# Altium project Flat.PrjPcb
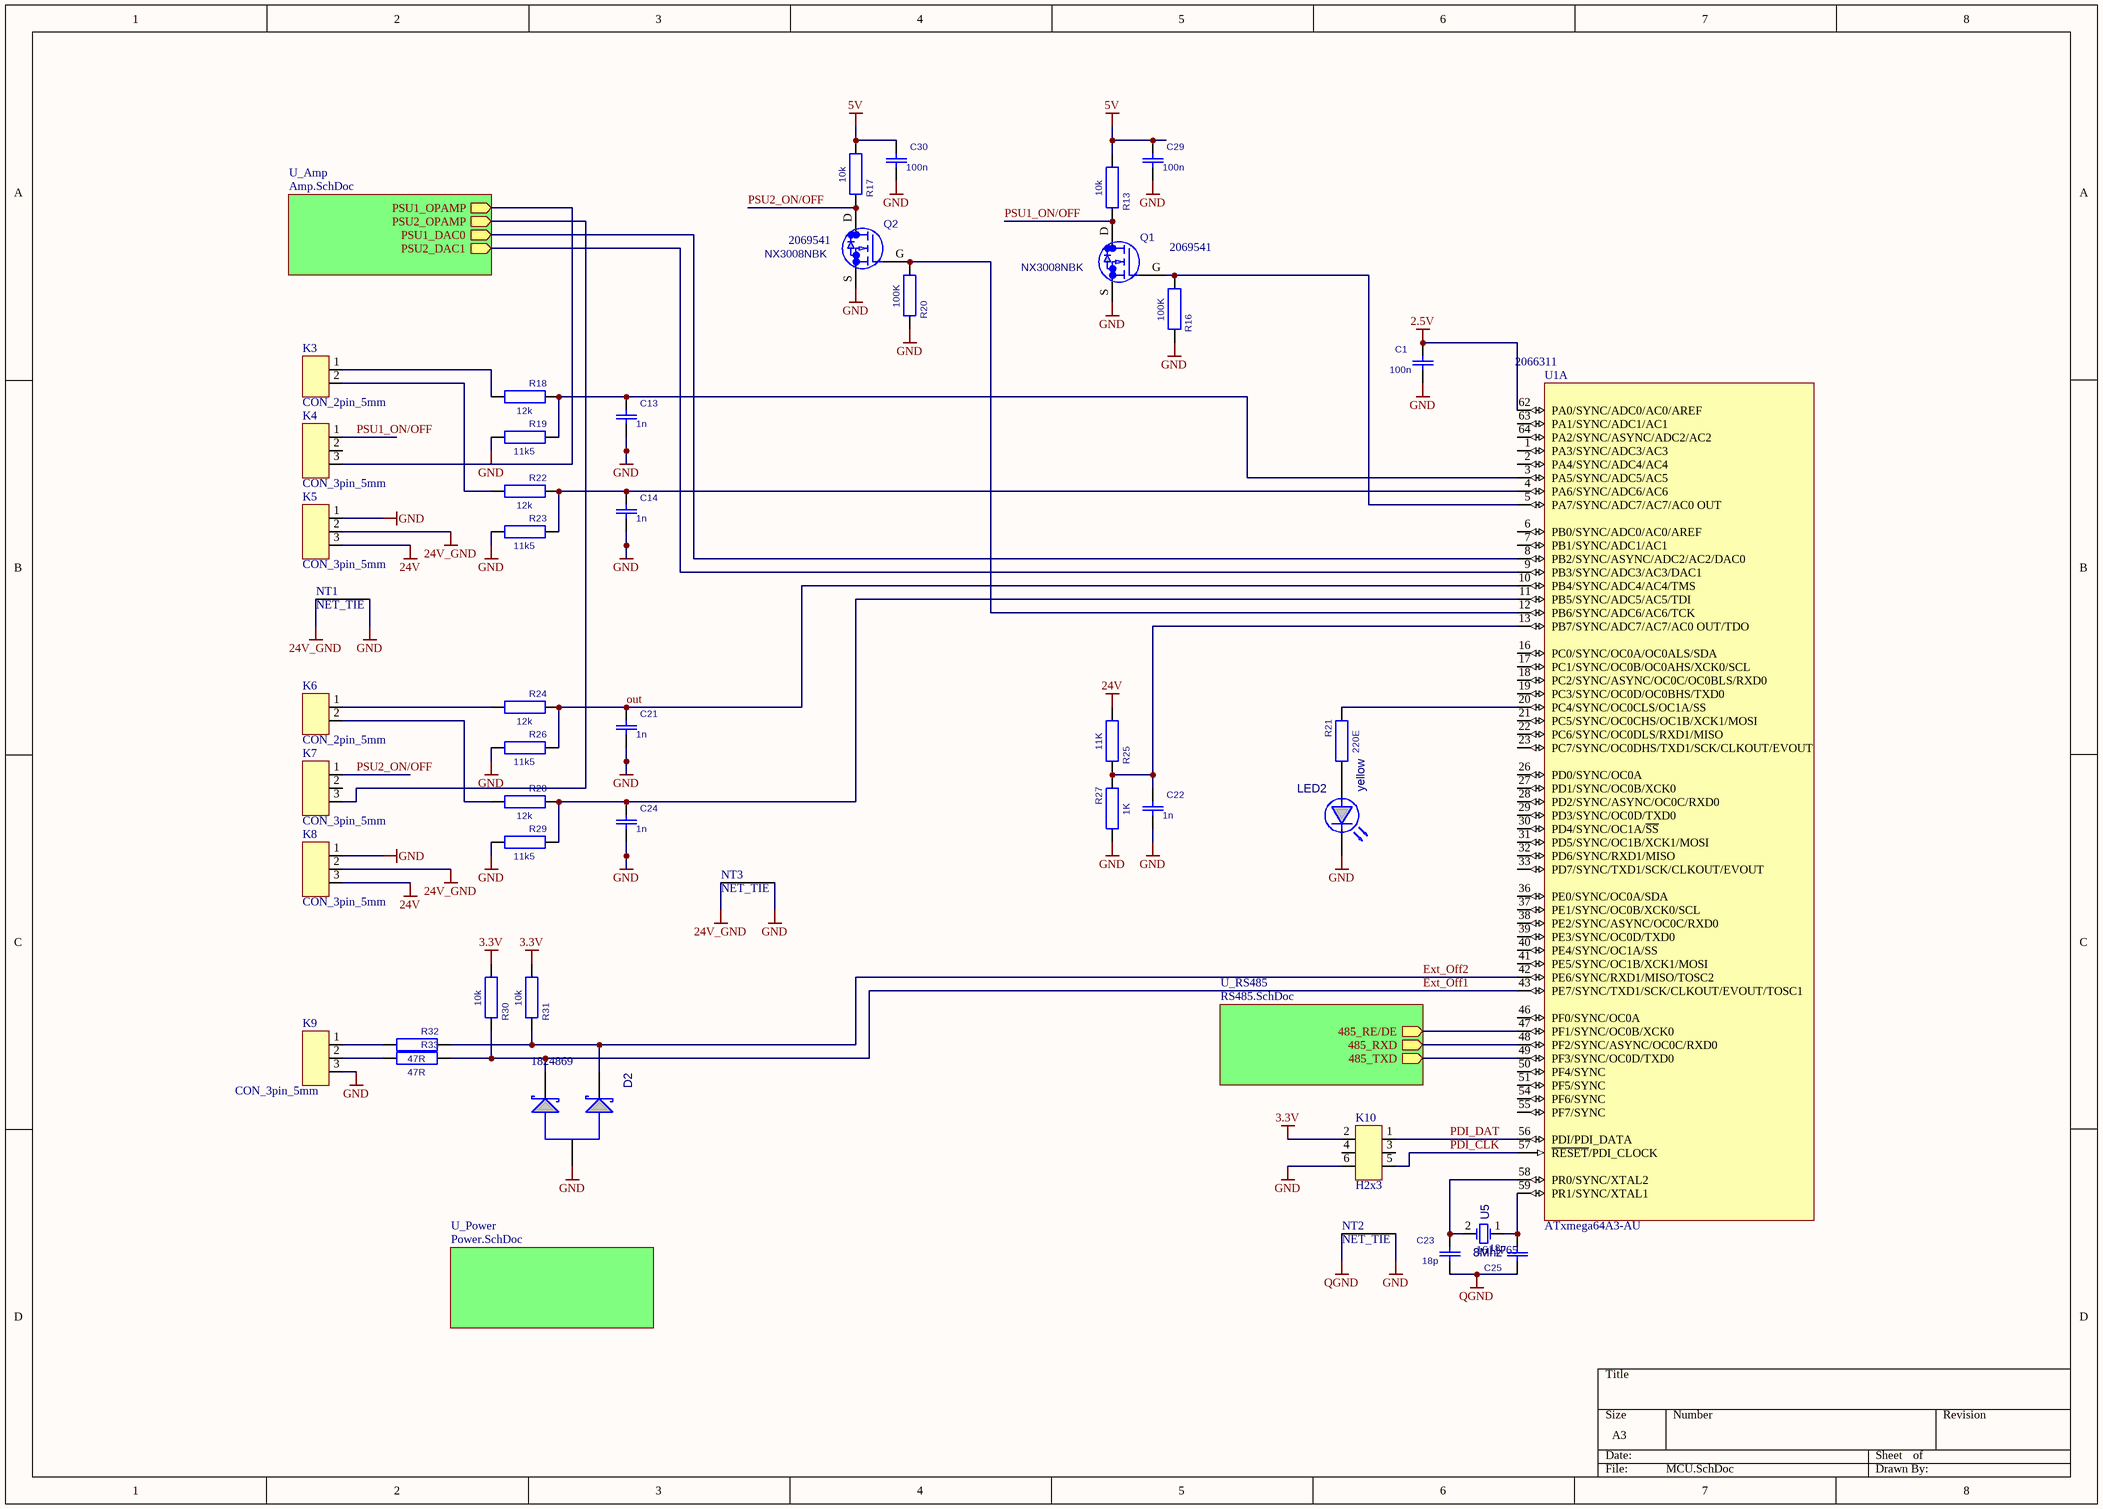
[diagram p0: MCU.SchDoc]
4 sheets, 95 parts. Net scope: hierarchical (ports join the sheet entries above them; power ports are global).
Board file: Flat.PcbDoc
Sheets:
  MCU.SchDoc
    U_Amp = Amp.SchDoc
    U_Power = Power.SchDoc
    U_RS485 = RS485.SchDoc

## Sheet MCU.SchDoc
size A3; SheetNumber: 1; SheetTotal: 4

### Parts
C1  100n  [C0805]
C13  1n  [C0805]
C14  1n  [C0805]
C21  1n  [C0805]
C22  1n  [C0805]
C23  18p  [C0805]
C24  1n  [C0805]
C25  18p  [C0805]
C29  100n  [C0805]
C30  100n  [C0805]
D2  Supplier Part Number 1: 1824869  [SOT-663]  (hidden comment: CDSOT23-SM712)
K3  CON_2pin_5mm  [CON_2pin_5mm]
K4  CON_3pin_5mm  [COM_3pin_5mm]
K5  CON_3pin_5mm  [COM_3pin_5mm]
K6  CON_2pin_5mm  [CON_2pin_5mm]
K7  CON_3pin_5mm  [COM_3pin_5mm]
K8  CON_3pin_5mm  [COM_3pin_5mm]
K9  CON_3pin_5mm  [COM_3pin_5mm]
K10  H2x3  [H2x3]
LED2  value yellow  [LED0805]  (hidden comment: LED0805)
NT1  NET_TIE  [NET_TIE_LINE]  (net tie, no BOM)
NT2  NET_TIE  [NET_TIE_LINE]  (net tie, no BOM)
NT3  NET_TIE  [NET_TIE_LINE]  (net tie, no BOM)
Q1  NX3008NBK  Supplier Part Number 1: 2069541  [SOT23(IRLML2502)]
Q2  NX3008NBK  Supplier Part Number 1: 2069541  [SOT23(IRLML2502)]
R13  10k  [R0805]
R16  100K  [R0805]
R17  10k  [R0805]
R18  12k  [R0805]
R19  11k5  [R0805]
R20  100K  [R0805]
R21  220E  [R0805]
R22  12k  [R0805]
R23  11k5  [R0805]
R24  12k  [R0805]
R25  11K  [R0805]
R26  11k5  [R0805]
R27  1K  [R0805]
R28  12k  [R0805]
R29  11k5  [R0805]
R30  10k  [R0805]
R31  10k  [R0805]
R32  47R  [R0805]
R33  47R  [R0805]
U1  ATxmega64A3-AU  Supplier Part Number 1: 2066311  [64A_M]  (part A of 2)
U5  8Mhz  Supplier Part Number 1: 1611765  [HC49/4H_SMX]

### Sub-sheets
U_Amp = Amp.SchDoc: PSU1_OPAMP (out), PSU2_OPAMP (out), PSU1_DAC0 (out), PSU2_DAC1 (out)
U_Power = Power.SchDoc: no entries
U_RS485 = RS485.SchDoc: 485_RE/DE (out), 485_TXD (out), 485_RXD (out)

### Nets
2.5V: C1.1 U1.62(PA0/SYNC/ADC0/AC0/AREF)
3.3V: K10.2 R30.2 R31.2
5V: C29.1 C30.1 R13.2 R17.2
24V: K5.3 K8.3 R25.2
24V_GND: K5.2 K8.2 NT1.1 NT3.1
GND: C1.2 C13.2 C14.2 C21.2 C22.2 C24.2 C29.2 C30.2 D2.2(A2) K5.1 K8.1 K9.3 K10.6 LED2.K NT1.2 NT2.2 NT3.2 Q1.S Q2.S R16.1 R19.2 R20.1 R23.2 R26.2 R27.2 R29.2
QGND: C23.2 C25.1 NT2.1
485_RE/DE: U1.47(PF1/SYNC/OC0B/XCK0) ; sheet U_RS485/485_RE/DE
485_RXD: U1.48(PF2/SYNC/ASYNC/OC0C/RXD0) ; sheet U_RS485/485_RXD
485_TXD: U1.49(PF3/SYNC/OC0D/TXD0) ; sheet U_RS485/485_TXD
Ext_Off1: D2.3(K) R30.1 R33.1 U1.43(PE7/SYNC/TXD1/SCK/CLKOUT/EVOUT/TOSC1)  [project net Ext_Off1_1]
Ext_Off2: D2.1(A1) R31.1 R32.1 U1.42(PE6/SYNC/RXD1/MISO/TOSC2)  [project net Ext_Off2_1]
out: C21.1 R24.1 R26.1 U1.10(PB4/SYNC/ADC4/AC4/TMS)  [project net out_1]
PDI_CLK: K10.5 U1.57(~{RESET}/PDI_CLOCK)  [project net PDI_CLK_1]
PDI_DAT: K10.1 U1.56(PDI/PDI_DATA)  [project net PDI_DAT_1]
PSU1_DAC0: U1.8(PB2/SYNC/ASYNC/ADC2/AC2/DAC0) ; sheet U_Amp/PSU1_DAC0
PSU1_ON/OFF: K4.1 Q1.D R13.1  [project net PSU1_ON/OFF_1]
PSU1_OPAMP: K4.3 ; sheet U_Amp/PSU1_OPAMP
PSU2_DAC1: U1.9(PB3/SYNC/ADC3/AC3/DAC1) ; sheet U_Amp/PSU2_DAC1
PSU2_ON/OFF: K7.1 Q2.D R17.1  [project net PSU2_ON/OFF_1]
PSU2_OPAMP: K7.3 ; sheet U_Amp/PSU2_OPAMP
NetC13_1: C13.1 R18.1 R19.1 U1.3(PA5/SYNC/ADC5/AC5)
NetC14_1: C14.1 R22.1 R23.1 U1.4(PA6/SYNC/ADC6/AC6)
NetC22_1: C22.1 R25.1 R27.1 U1.13(PB7/SYNC/ADC7/AC7/AC0_OUT/TDO)
NetC23_1: C23.1 U1.58(PR0/SYNC/XTAL2) U5.2(OSC2)
NetC24_1: C24.1 R28.1 R29.1 U1.11(PB5/SYNC/ADC5/AC5/TDI)
NetC25_2: C25.2 U1.59(PR1/SYNC/XTAL1) U5.1(OSC1)
NetK3_1: K3.1 R18.2
NetK3_2: K3.2 R22.2
NetK6_1: K6.1 R24.2
NetK6_2: K6.2 R28.2
NetK9_1: K9.1 R32.2
NetK9_2: K9.2 R33.2
NetLED2_A: LED2.A R21.2
NetQ1_G: Q1.G R16.2 U1.5(PA7/SYNC/ADC7/AC7/AC0_OUT)
NetQ2_G: Q2.G R20.2 U1.12(PB6/SYNC/ADC6/AC6/TCK)
NetR21_1: R21.1 U1.20(PC4/SYNC/OC0CLS/OC1A/SS)

Not connected (* = marked no-connect by the designer): K4 2; K7 2; K10 3 4; U1 1(PA3/SYNC/ADC3/AC3) 2(PA4/SYNC/ADC4/AC4) 6(PB0/SYNC/ADC0/AC0/AREF) 7(PB1/SYNC/ADC1/AC1) 16(PC0/SYNC/OC0A/OC0ALS/SDA) 17(PC1/SYNC/OC0B/OC0AHS/XCK0/SCL) 18(PC2/SYNC/ASYNC/OC0C/OC0BLS/RXD0) 19(PC3/SYNC/OC0D/OC0BHS/TXD0) 21(PC5/SYNC/OC0CHS/OC1B/XCK1/MOSI) 22(PC6/SYNC/OC0DLS/RXD1/MISO) 23(PC7/SYNC/OC0DHS/TXD1/SCK/CLKOUT/EVOUT) 26(PD0/SYNC/OC0A) 27(PD1/SYNC/OC0B/XCK0) 28(PD2/SYNC/ASYNC/OC0C/RXD0) 29(PD3/SYNC/OC0D/TXD0) 30(PD4/SYNC/OC1A/~{SS}) 31(PD5/SYNC/OC1B/XCK1/MOSI) 32(PD6/SYNC/RXD1/MISO) 33(PD7/SYNC/TXD1/SCK/CLKOUT/EVOUT) 36(PE0/SYNC/OC0A/SDA) 37(PE1/SYNC/OC0B/XCK0/SCL) 38(PE2/SYNC/ASYNC/OC0C/RXD0) 39(PE3/SYNC/OC0D/TXD0) 40(PE4/SYNC/OC1A/SS) 41(PE5/SYNC/OC1B/XCK1/MOSI) 46(PF0/SYNC/OC0A) 50(PF4/SYNC) 51(PF5/SYNC) 54(PF6/SYNC) 55(PF7/SYNC) 63(PA1/SYNC/ADC1/AC1) 64(PA2/SYNC/ASYNC/ADC2/AC2)

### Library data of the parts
C1 C13 C14 C21-C25 C29 C30 = SMD CAPACITOR: SMD Chip Capacitor; Tolerance: {Tolerance}
D2 = BAT54A: pin to pad: 2>3 3>2; ComponentLink2DescA4: Datasheet; Note: Pin 2 is not connected and is not drawn; ComponentLink1DescBC: Manufacturer Link
K3 K6 = CON_2pin_5mm: Konektor za  Bernic ohišja Serija 605, 5 mm raster
K4 K5 K7-K9 = CON_3pin_5mm: Konektor za Bernic ohišja, 5 mm
K10 = H2x3: Header 2x3 (male)
LED2 = LED0805: Chip LED diode
Q1 Q2 = IRLML2502: Value: {Value}
R13 R16-R33 = SMD RESISTOR: Surface mount resistor; Power: {Power}
U1 = ATxmega64A3-AU: 8/16-bit AVR XMEGA A3 Microcontroller, 1.6-3.6V, 32MHz, 64KB + 4KB Flash, 2KB EEPROM, 4KB SRAM, 64-pin TQFP, Industrial Grade (-40°C to 85°C), Pb-Free
U5 = Q HC49 SMD: Q SMD; ComponentLink2DescA4: Datasheet; Note: PCB layout complies with manufacturer's recommendation.; ComponentLink1DescBC: Manufacturer Link

## Sheet Amp.SchDoc
size A4; SheetNumber: 3; SheetTotal: 4
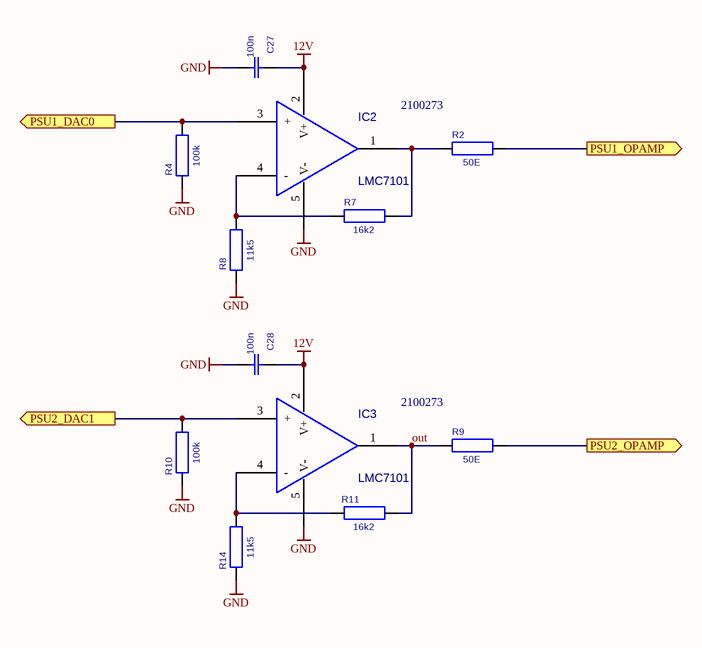
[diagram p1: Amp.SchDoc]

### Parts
C27  100n  [C0805]
C28  100n  [C0805]
IC2  LMC7101  Supplier Part Number 1: 2100273  [SO-G5/P.95]
IC3  LMC7101  Supplier Part Number 1: 2100273  [SO-G5/P.95]
R2  50E  [R0805]
R4  100k  [R0805]
R7  16k2  [R0805]
R8  11k5  [R0805]
R9  50E  [R0805]
R10  100k  [R0805]
R11  16k2  [R0805]
R14  11k5  [R0805]

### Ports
PSU1_DAC0 (out), PSU1_OPAMP (out), PSU2_DAC1 (out), PSU2_OPAMP (out)

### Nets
12V: C27.1 C28.1 IC2.2(V+) IC3.2(V+)
GND: C27.2 C28.2 IC2.5(V-) IC3.5(V-) R4.1 R8.1 R10.1 R14.1
out: IC3.1 R9.1 R11.2  [project net out_3]
PSU1_DAC0: IC2.3(+) R4.2 ; port PSU1_DAC0
PSU1_OPAMP: R2.2 ; port PSU1_OPAMP
PSU2_DAC1: IC3.3(+) R10.2 ; port PSU2_DAC1
PSU2_OPAMP: R9.2 ; port PSU2_OPAMP
NetIC2_1: IC2.1 R2.1 R7.2
NetIC2_4: IC2.4(-) R7.1 R8.2
NetIC3_4: IC3.4(-) R11.1 R14.2

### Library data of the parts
C27 C28 = SMD CAPACITOR: as C1 on sheet MCU
R2 R4 R7-R11 R14 = SMD RESISTOR: Surface mount resistor; Power: {Power}

## Sheet Power.SchDoc
size A4; SheetNumber: 4; SheetTotal: 4
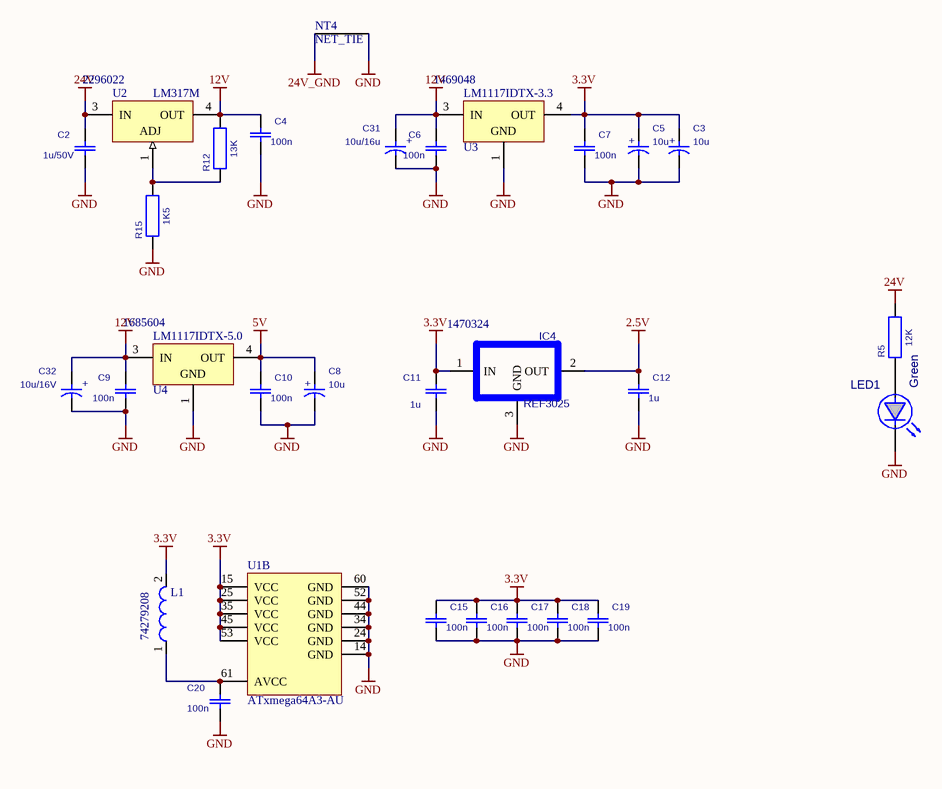
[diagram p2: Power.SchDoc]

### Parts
C2  1u/50V  [C0805]
C3  10u  [CT_A]
C4  100n  [C0805]
C5  10u  [CT_A]
C6  100n  [C0805]
C7  100n  [C0805]
C8  10u  [CT_A]
C9  100n  [C0805]
C10  100n  [C0805]
C11  1u  [C0805]
C12  1u  [C0805]
C15  100n  [C0805]
C16  100n  [C0805]
C17  100n  [C0805]
C18  100n  [C0805]
C19  100n  [C0805]
C20  100n  [C0805]
C31  10u/16u  [CT_A]
C32  10u/16V  [CT_A]
IC4  REF3025  Supplier Part Number 1: 1470324  [SOT23]
L1  74279208  [SMD-0805]
LED1  value Green  [LED0805]  (hidden comment: LED0805)
NT4  NET_TIE  [NET_TIE_LINE]  (net tie, no BOM)
R5  12K  [R0805]
R12  13K  [R0805]
R15  1K5  [R0805]
U1  ATxmega64A3-AU  [64A_N]  (part B of 2)
U2  LM317M  Supplier Part Number 1: 2296022  [TD03B_M]
U3  LM1117IDTX-3.3  Supplier Part Number 1: 1469048  [TD03B_M]
U4  LM1117IDTX-5.0  Supplier Part Number 1: 1685604  [TD03B_M]

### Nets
2.5V: C12.1 IC4.2(OUT)
3.3V: C3.1 C5.1 C7.1 C11.1 C15.1 C16.1 C17.1 C18.1 C19.1 IC4.1(IN) L1.2 U1.15(VCC) U1.25(VCC) U1.35(VCC) U1.45(VCC) U1.53(VCC) U3.4(OUT)
5V: C8.1 C10.1 U4.4(OUT)
12V: C4.1 C6.1 C9.1 C31.1 C32.1 R12.2 U2.4(OUT) U3.3(IN) U4.3(IN)
24V: C2.1 R5.2 U2.3(IN)
24V_GND: NT4.1
GND: C2.2 C3.2 C4.2 C5.2 C6.2 C7.2 C8.2 C9.2 C10.2 C11.2 C12.2 C15.2 C16.2 C17.2 C18.2 C19.2 C20.2 C31.2 C32.2 IC4.3(GND) LED1.K NT4.2 R15.1 U1.14(GND) U1.24(GND) U1.34(GND) U1.44(GND) U1.52(GND) U1.60(GND) U3.1(GND) U4.1(GND)
NetC20_1: C20.1 L1.1 U1.61(AVCC)
NetLED1_A: LED1.A R5.1
NetR12_1: R12.1 R15.2 U2.1(ADJ)

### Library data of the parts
C2 C4 C6 C7 C9-C12 C15-C20 = SMD CAPACITOR: as C1 on sheet MCU
C3 C5 C8 C31 C32 = CT_A: {Description}; RefProducer: {RefProducer}; Geometry: {Geometry}; Tolerance: {Tolerance}; MinESR: {MinESR}; MaxESR: {MaxESR}; SolventProof: {SolventProof}; LifeTime: {LifeTime}; TempRange: {TempRange}; Reference: {Reference}; RefProducerCode: {RefProducerCode}; Z(-25deg)/Z(+20deg): {Z(-25deg)/Z(+20deg)}; MaxLeakageCurrent: {MaxLeakageCurrent}; MinRippleCurrent: {MinRippleCurrent}
IC4 = REF3040
L1 = 74279208: SMD EMI Suppression Ferrite Bead WE-CBF, Z = 40 Ohm; Impedance: 40 Ohm
LED1 = LED0805: Chip LED diode
R5 R12 R15 = SMD RESISTOR: Surface mount resistor; Power: {Power}
U1 = ATxmega64A3-AU: as U1 on sheet MCU
U2 = LM317MDT: 3-Terminal Adjustable Regulator, 3-pin TO-252; Manufacturer: National Semiconductor; PackageTopMarking: NSUZXYTT*LM317*MDT; PowerWise: N; CompType: LDO IC; High-Reliability: Y
U3 = LM1117IDTX-3.3: 800mA Low-Dropout Linear Regulator, 3-pin TO-252; Manufacturer: National Semiconductor; PackageTopMarking: NSUZXYTT*LM1117*IDT-3.3; PowerWise: N; CompType: LDO IC; High-Reliability: Y
U4 = LM1117IDTX-5.0: 800mA Low-Dropout Linear Regulator, 3-pin TO-252; Manufacturer: National Semiconductor; PackageTopMarking: NSUZXYTT*LM1117*IDT-5.0; PowerWise: N; CompType: LDO IC; High-Reliability: Y

## Sheet RS485.SchDoc
size A4; SheetNumber: 2; SheetTotal: 4
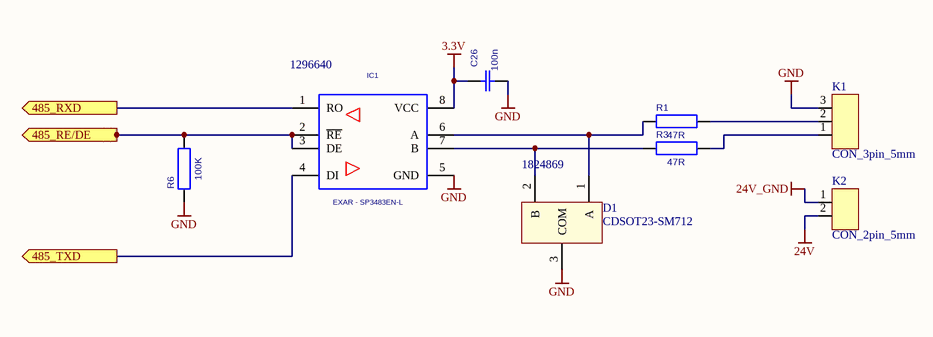
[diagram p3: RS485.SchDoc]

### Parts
C26  100n  [C0805]
D1  CDSOT23-SM712  Supplier Part Number 2: 1824869  [SOT23(BAT54)]
IC1  EXAR - SP3483EN-L  Supplier Part Number 1: 1296640  [SO8R]
K1  CON_3pin_5mm  [COM_3pin_5mm]
K2  CON_2pin_5mm  [CON_2pin_5mm]
R1  47R  [R0805]
R3  47R  [R0805]
R6  100K  [R0805]

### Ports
485_RE/DE (out), 485_RXD (out), 485_TXD (out)

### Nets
3.3V: C26.1 IC1.8(VCC)
24V: K2.2
24V_GND: K2.1
GND: C26.2 D1.3(COM) IC1.5(GND) K1.3 R6.1
485_RE/DE: IC1.2(~{RE}) IC1.3(DE) R6.2 ; off-sheet 485_RE/DE, port 485_RE/DE
485_RXD: IC1.1(RO) ; port 485_RXD
485_TXD: IC1.4(DI) ; port 485_TXD
NetD1_1: D1.1(A) IC1.6(A) R1.1
NetD1_2: D1.2(B) IC1.7(B) R3.1
NetK1_1: K1.1 R3.2
NetK1_2: K1.2 R1.2

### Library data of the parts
C26 = SMD CAPACITOR: as C1 on sheet MCU
IC1 = MAX485CSA_(SO8): Line-Powered RS-232 Transceiver Chip; OriginalName: DS1275S; Value: {Value}; ComponentField6: Pin number 6 is Not Connected (NC); ComponentField7: Published 13-Oct-2000
K1 = CON_3pin_5mm: Konektor za Bernic ohišja, 5 mm
K2 = CON_2pin_5mm: as K3 on sheet MCU
R1 R3 R6 = SMD RESISTOR: Surface mount resistor; Power: {Power}

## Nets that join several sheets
2.5V: MCU (C1.1 U1.62), Power (C12.1 IC4.2)
3.3V: MCU (K10.2 R30.2 R31.2), Power (17 pins), RS485 (C26.1 IC1.8)
5V: MCU (C29.1 C30.1 R13.2 R17.2), Power (C8.1 C10.1 U4.4)
12V: Amp (C27.1 C28.1 IC2.2 IC3.2), Power (9 pins)
24V: MCU (K5.3 K8.3 R25.2), Power (C2.1 R5.2 U2.3), RS485 (K2.2)
24V_GND: MCU (K5.2 K8.2 NT1.1 NT3.1), Power (NT4.1), RS485 (K2.1)
GND: MCU (26 pins), Amp (8 pins), Power (31 pins), RS485 (5 pins)
485_RE/DE: MCU (U1.47), RS485 (IC1.2 IC1.3 R6.2)
485_RXD: MCU (U1.48), RS485 (IC1.1)
485_TXD: MCU (U1.49), RS485 (IC1.4)
PSU1_DAC0: MCU (U1.8), Amp (IC2.3 R4.2)
PSU1_OPAMP: MCU (K4.3), Amp (R2.2)
PSU2_DAC1: MCU (U1.9), Amp (IC3.3 R10.2)
PSU2_OPAMP: MCU (K7.3), Amp (R9.2)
